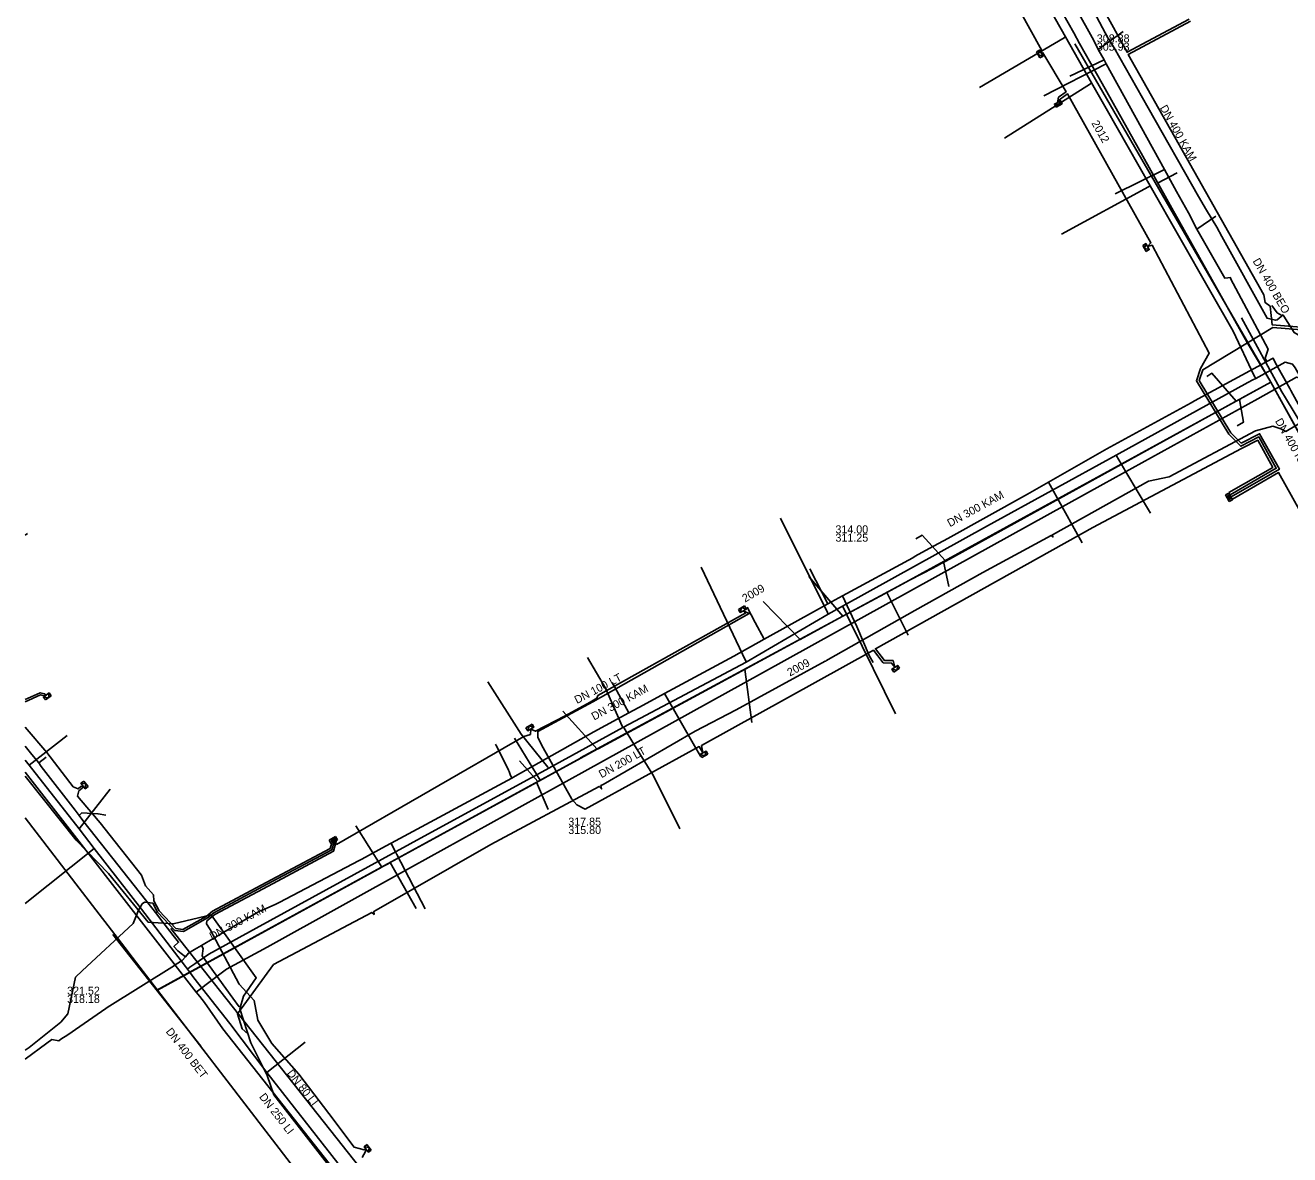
# Model space of a CAD drawing. Extents: x -600391 to -599491, y -1160176 to -1159402.
# Drawn here: x -600391 to -600264.6, y -1159907.9 to -1159795.1 of the extents above; entities that cross this region are included whole.
import ezdxf

# ---------------------------------------------------------------- set-up
doc = ezdxf.new("R2010")
doc.units = 0
for name, color, linetype in [('28', 7, 'Continuous'), ('31', 7, 'Continuous'), ('Vrstva 1', 7, 'Continuous'), ('Vrstva 12', 7, 'Continuous'), ('Vrstva 13', 7, 'Continuous'), ('Vrstva 15', 7, 'Continuous'), ('Vrstva 16', 7, 'Continuous'), ('Vrstva 19', 7, 'Continuous'), ('Vrstva 42', 7, 'Continuous'), ('Vrstva 43', 7, 'Continuous'), ('Vrstva 55', 7, 'Continuous'), ('Vrstva 9', 7, 'Continuous')]:
    doc.layers.add(name, color=color, linetype=linetype)

# ---------------------------------------------------------------- blocks, each defined once
blk = doc.blocks.new('NN630')
at = {"layer": '31'}
for points in [[(0, -0.7), (-0.7, 0)], [(-0.7, -0.7), (-0.7, 0), (0.7, 0), (0.7, -0.7)], [(-0.7, -0.7), (0.7, -0.7)], [(0, -0.7), (0.7, 0)]]:
    blk.add_lwpolyline(points, dxfattribs=at)
blk = doc.blocks.new('NN620')
at = {"layer": '28'}
for points in [[(0.75, 0), (-0.75, 0)], [(-0.75, 0), (-0.75, -0.75)], [(0.75, -0.75), (0.75, 0)], [(-0.75, -0.75), (0.75, -0.75)], [(0.37, -0.18), (-0.38, -0.18)], [(-0.38, -0.18), (-0.38, -0.56)], [(-0.38, -0.56), (0.37, -0.56)], [(0.32, -0.23), (-0.33, -0.23)], [(-0.33, -0.23), (-0.33, -0.51)], [(-0.33, -0.51), (0.32, -0.51)], [(0.27, -0.27), (-0.28, -0.27)], [(-0.28, -0.27), (-0.28, -0.46)], [(-0.28, -0.46), (0.27, -0.46)], [(0.23, -0.32), (-0.23, -0.32)], [(-0.23, -0.32), (-0.23, -0.42)], [(-0.23, -0.42), (0.23, -0.42)], [(-0.19, -0.37), (0.19, -0.37)], [(0.23, -0.42), (0.23, -0.32)], [(0.27, -0.46), (0.27, -0.27)], [(0.32, -0.51), (0.32, -0.23)], [(0.37, -0.56), (0.37, -0.18)]]:
    blk.add_lwpolyline(points, dxfattribs=at)

msp = doc.modelspace()

# ---------------------------------------------------------------- linework, layer by layer
at = {"layer": 'Vrstva 1'}
for points in [[(-600266.53, -1159830.73), (-600286.12, -1159796.92)], [(-600275.88, -1159809.81), (-600277.84, -1159810.83)], [(-600272.94, -1159830.17), (-600272.41, -1159829.84), (-600269.98, -1159832.62)], [(-600266.53, -1159830.73), (-600302.63, -1159850.52)], [(-600254.35, -1159852.71), (-600266.53, -1159830.73)], [(-600269.9, -1159835.08), (-600269.27, -1159834.73), (-600269.67, -1159832.45)], [(-600299.06, -1159848.55), (-600301.38, -1159846.02), (-600302.01, -1159846.37)], [(-600299.24, -1159848.65), (-600298.7, -1159851.13)], [(-600302.63, -1159850.52), (-600335.52, -1159868.27)], [(-600309.3, -1159854.11), (-600312.71, -1159850.14)], [(-600304.91, -1159851.74), (-600302.76, -1159856.02)], [(-600313.58, -1159856.42), (-600317.27, -1159852.64)], [(-600318.41, -1159864.72), (-600319.08, -1159859.39)], [(-600333.86, -1159867.38), (-600337.27, -1159863.61)], [(-600339.56, -1159870.49), (-600342.12, -1159866.31)], [(-600335.52, -1159868.28), (-600377.87, -1159891.49)], [(-600339.77, -1159870.61), (-600341.61, -1159868.57)], [(-600339.93, -1159870.7), (-600338.76, -1159873.42)], [(-600357.98, -1159875.06), (-600355.38, -1159879.17)], [(-600354.54, -1159878.71), (-600351.94, -1159883.33)], [(-600382.26, -1159885.91), (-600373.48, -1159897.07)]]:
    msp.add_lwpolyline(points, dxfattribs=at)
at = {"layer": 'Vrstva 13'}
for p, q in [((-600270.29, -1159825.64), (-600268.19, -1159830.08)), ((-600268.32, -1159830.5), (-600268.04, -1159830.35)), ((-600268.19, -1159830.08), (-600268.04, -1159830.35)), ((-600391.01, -1159846.01), (-600390.8, -1159845.85)), ((-600390.63, -1159868.99), (-600386.81, -1159866.03)), ((-600385.63, -1159875.35), (-600382.53, -1159871.38)), ((-600384.14, -1159877.32), (-600391.01, -1159882.83)), ((-600379.39, -1159883.39), (-600375.01, -1159889.1)), ((-600378.45, -1159885.84), (-600373.92, -1159891.66)), ((-600375.01, -1159889.1), (-600374.8, -1159889.38)), ((-600374.8, -1159889.38), (-600374.55, -1159889.19)), ((-600374.8, -1159889.38), (-600374.6, -1159889.65)), ((-600374.6, -1159889.65), (-600374.51, -1159889.78)), ((-600373.92, -1159891.66), (-600373.54, -1159891.36)), ((-600373.92, -1159891.66), (-600373.56, -1159892.11)), ((-600366.86, -1159899.69), (-600363.05, -1159896.67))]:
    msp.add_line(p, q, dxfattribs=at)
for points in [[(-600318.46, -1159740.43), (-600311.31, -1159753.11), (-600311.18, -1159753.34), (-600308.82, -1159757.52), (-600308.39, -1159758.3), (-600301.63, -1159770.35), (-600298.43, -1159776.06), (-600297.79, -1159777.2), (-600296.56, -1159779.37), (-600292.54, -1159786.5), (-600291.67, -1159788.04), (-600288.04, -1159794.45), (-600287.04, -1159796.22), (-600284.44, -1159800.82), (-600282.98, -1159803.38), (-600278.58, -1159811.11), (-600272.65, -1159821.5), (-600270.29, -1159825.64)], [(-600287.04, -1159796.22), (-600287.19, -1159796.31), (-600295.64, -1159801.28)], [(-600284.44, -1159800.82), (-600284.56, -1159800.9), (-600293.16, -1159806.35)], [(-600278.58, -1159811.11), (-600278.75, -1159811.21), (-600287.46, -1159815.94)], [(-600268.04, -1159830.35), (-600265.11, -1159828.73), (-600264.36, -1159828.93), (-600264.11, -1159829.29), (-600263.68, -1159829.99), (-600263.48, -1159830.35), (-600250.95, -1159852.35), (-600246.5, -1159860.12), (-600238.23, -1159874.5), (-600236.83, -1159876.89), (-600236.21, -1159877.98)], [(-600374.55, -1159889.19), (-600374.05, -1159888.85), (-600372.67, -1159887.87), (-600367.94, -1159885.27), (-600352.53, -1159876.85), (-600338.69, -1159869.28), (-600331.3, -1159865.24), (-600331.21, -1159865.2), (-600318.95, -1159858.71), (-600310.78, -1159853.89), (-600309.34, -1159853.1), (-600294.83, -1159845.09), (-600281.99, -1159838.01), (-600268.81, -1159830.77), (-600268.32, -1159830.5)], [(-600373.54, -1159891.36), (-600372.93, -1159890.91), (-600370.89, -1159889.39), (-600366.85, -1159887.18), (-600352.31, -1159879.13), (-600335.08, -1159869.59), (-600317.34, -1159859.78), (-600300.08, -1159850.22), (-600283.27, -1159840.92), (-600267.84, -1159832.38), (-600263.95, -1159830.23), (-600262.43, -1159830.62), (-600255.08, -1159843.6), (-600247.73, -1159856.58), (-600236, -1159876.75), (-600235.14, -1159876.86), (-600231.99, -1159875.01), (-600217.64, -1159866.82), (-600199.23, -1159856.44), (-600175.64, -1159843.1), (-600159.56, -1159834.39), (-600159.03, -1159834.09)], [(-600281.99, -1159838.01), (-600281.94, -1159838.1), (-600281.01, -1159839.67), (-600278.54, -1159843.82)], [(-600310.78, -1159853.89), (-600310.85, -1159853.75), (-600315.54, -1159844.31)], [(-600318.95, -1159858.71), (-600319, -1159858.61), (-600323.47, -1159849.2)], [(-600309.34, -1159853.1), (-600309.28, -1159853.22), (-600308.47, -1159854.87), (-600304.04, -1159863.86)], [(-600331.3, -1159865.24), (-600331.36, -1159865.1), (-600333.02, -1159861.3), (-600334.83, -1159858.24)], [(-600338.69, -1159869.28), (-600338.77, -1159869.18), (-600341.44, -1159865.88), (-600344.79, -1159860.67)], [(-600331.21, -1159865.2), (-600331.17, -1159865.28), (-600330.18, -1159866.89), (-600328.24, -1159870.07), (-600325.59, -1159875.36)], [(-600391.01, -1159868.51), (-600390.63, -1159868.99), (-600385.63, -1159875.35), (-600384.14, -1159877.32), (-600379.39, -1159883.39)], [(-600391.01, -1159869.68), (-600384.73, -1159877.8), (-600378.45, -1159885.84)], [(-600374.51, -1159889.78), (-600374.17, -1159890.23), (-600370.56, -1159894.82)], [(-600373.56, -1159892.11), (-600373.11, -1159892.72), (-600371.27, -1159895.33)], [(-600370.56, -1159894.82), (-600366.86, -1159899.69), (-600357.62, -1159911.54), (-600356.84, -1159912.52), (-600341.12, -1159932.99), (-600339.37, -1159935.25), (-600334.21, -1159941.97), (-600326.67, -1159951.39), (-600325.09, -1159953.46), (-600321.88, -1159957.77), (-600316.54, -1159964.25), (-600309.48, -1159972.8)], [(-600371.27, -1159895.33), (-600358.15, -1159911.95), (-600339.79, -1159935.58), (-600327.19, -1159951.77), (-600317.13, -1159964.71), (-600308.66, -1159975.6)]]:
    msp.add_lwpolyline(points, dxfattribs=at)
at = {"layer": 'Vrstva 16'}
msp.add_lwpolyline([(-600149.13, -1160176.08), (-600149.77, -1160175.26), (-600153.28, -1160170.92), (-600160.82, -1160161.59), (-600162.37, -1160159.57), (-600191.81, -1160121.42), (-600215.03, -1160091.66), (-600218.37, -1160087.39), (-600241.27, -1160058.04), (-600268.45, -1160023.15), (-600268.66, -1160022.86), (-600279.96, -1160008.45), (-600285.15, -1160001.76), (-600292.76, -1159991.95), (-600306.26, -1159974.55), (-600310.89, -1159968.58), (-600323.17, -1159952.95), (-600331.19, -1159942.75), (-600331.3, -1159942.61), (-600336.91, -1159935.47), (-600352.95, -1159915.04), (-600356.32, -1159910.78), (-600372.09, -1159890.83), (-600376.45, -1159885.3)], dxfattribs=at)
at = {"layer": 'Vrstva 19'}
for points in [[(-600287.66, -1159790.4), (-600284.23, -1159796.59), (-600283.8, -1159797.49), (-600283.17, -1159798.5), (-600283, -1159798.92), (-600277.16, -1159809.47), (-600275.95, -1159811.66), (-600274.75, -1159813.8), (-600273.93, -1159815.43), (-600271.13, -1159820.33), (-600270.53, -1159820.26)], [(-600283.8, -1159797.49), (-600281.29, -1159795.68)], [(-600283, -1159798.92), (-600289.2, -1159802.12)], [(-600283.17, -1159798.5), (-600286.61, -1159800.15)], [(-600277.16, -1159809.47), (-600282.08, -1159811.91)], [(-600273.93, -1159815.43), (-600272.01, -1159814.14)], [(-600266.92, -1159828.65), (-600267.09, -1159828.33), (-600266.8, -1159827.42), (-600270.55, -1159820.36), (-600270.53, -1159820.26)], [(-600261.41, -1159838.35), (-600265.07, -1159832.29), (-600265.42, -1159831.69), (-600269.46, -1159824.28)], [(-600266.92, -1159828.65), (-600267.46, -1159828.95), (-600274.14, -1159832.6), (-600274.49, -1159832.78), (-600282.92, -1159837.39), (-600288.74, -1159840.73), (-600290.83, -1159841.93), (-600298.81, -1159846.33), (-600300.68, -1159847.36), (-600302.06, -1159848.12), (-600302.31, -1159848.26), (-600309.33, -1159852.07), (-600310.8, -1159852.87), (-600311.95, -1159853.5), (-600317.17, -1159856.4), (-600320.2, -1159858.09), (-600327.11, -1159861.82), (-600329.27, -1159862.99), (-600330.7, -1159863.77), (-600334.2, -1159865.67), (-600342.04, -1159870.09), (-600342.37, -1159870.28), (-600354.44, -1159876.78), (-600355.01, -1159877.09), (-600357.38, -1159878.39), (-600357.64, -1159878.53), (-600365.63, -1159882.7)], [(-600235.81, -1159871.96), (-600240.31, -1159874.37), (-600240.85, -1159873.47), (-600242.66, -1159870.41), (-600247.12, -1159862.9), (-600248.85, -1159859.8), (-600250.34, -1159857.14), (-600257.66, -1159844.02), (-600258.74, -1159842.09), (-600261.4, -1159837.25), (-600264.53, -1159831.56), (-600264.64, -1159831.36), (-600266.08, -1159828.75), (-600266.31, -1159828.32), (-600266.92, -1159828.65)], [(-600288.74, -1159840.73), (-600286.01, -1159845.66), (-600285.39, -1159846.78)], [(-600310.8, -1159852.87), (-600312.61, -1159849.38)], [(-600309.33, -1159852.07), (-600307.9, -1159855.13), (-600306.66, -1159858.05), (-600306.26, -1159858.72)], [(-600317.17, -1159856.4), (-600318.06, -1159854.75), (-600318.86, -1159853.19)], [(-600330.7, -1159863.77), (-600332.1, -1159861.2), (-600332.35, -1159860.74)], [(-600327.11, -1159861.82), (-600323.99, -1159867.3), (-600323.53, -1159868.11)], [(-600391.01, -1159867.1), (-600390.36, -1159867.94), (-600389.67, -1159868.77), (-600389.43, -1159869.12), (-600386.03, -1159873.48), (-600385.62, -1159874.01), (-600385.17, -1159874.66), (-600377.87, -1159883.89), (-600377.29, -1159884.64), (-600377.14, -1159884.84)], [(-600344, -1159866.91), (-600343.95, -1159867.02), (-600343.19, -1159868.54), (-600342.72, -1159869.48)], [(-600389.67, -1159868.77), (-600388.92, -1159868.2)], [(-600342.72, -1159869.48), (-600342.64, -1159869.64), (-600342.56, -1159869.92), (-600342.37, -1159870.28)], [(-600385.62, -1159874.01), (-600385.37, -1159873.76), (-600383.77, -1159873.87), (-600383.71, -1159873.84)], [(-600383.71, -1159873.84), (-600382.95, -1159873.99)], [(-600354.44, -1159876.78), (-600354.26, -1159877.14), (-600354, -1159877.65), (-600353.87, -1159877.91)], [(-600353.87, -1159877.91), (-600351.06, -1159883.36)], [(-600365.63, -1159882.7), (-600366.04, -1159882.9), (-600367.16, -1159883.43), (-600367.53, -1159883.54), (-600371.16, -1159885.68), (-600372.18, -1159886.28), (-600373.4, -1159887)], [(-600375.44, -1159887.8), (-600375.76, -1159887.54), (-600376.15, -1159887.12), (-600375.68, -1159886.69), (-600376.24, -1159886.02), (-600377.14, -1159884.84)], [(-600373.4, -1159887), (-600374.09, -1159887.42), (-600374.7, -1159887.79), (-600375, -1159888.14), (-600375.32, -1159888.51), (-600375.93, -1159888.89), (-600376.11, -1159889), (-600382.81, -1159893.22), (-600382.96, -1159893.32), (-600385.56, -1159895.1), (-600386.77, -1159895.94), (-600387.45, -1159896.37)], [(-600373.4, -1159887), (-600373.22, -1159887.31), (-600373.34, -1159888.03), (-600370.28, -1159892.26), (-600369.64, -1159893.15)], [(-600375, -1159888.14), (-600375.44, -1159887.8)], [(-600391.01, -1159898.38), (-600388.84, -1159896.76), (-600388.36, -1159896.41), (-600387.64, -1159896.53), (-600387.45, -1159896.37)]]:
    msp.add_lwpolyline(points, dxfattribs=at)
at = {"layer": 'Vrstva 42'}
for points in [[(-600294.74, -1159787.93), (-600289.43, -1159797.58), (-600289.47, -1159797.84), (-600289.31, -1159797.8), (-600286.99, -1159801.7), (-600287.76, -1159802.26), (-600287.84, -1159802.77), (-600287.57, -1159802.43), (-600286.86, -1159801.91), (-600278.52, -1159816.81), (-600278.85, -1159817.18), (-600278.4, -1159817.03), (-600272.68, -1159827.82), (-600273.54, -1159829.37), (-600273.96, -1159830.59), (-600270.71, -1159835.93), (-600269.53, -1159837.12), (-600267.74, -1159836.19), (-600265.99, -1159839.33), (-600270.6, -1159841.98)], [(-600274.69, -1159794.44), (-600280.89, -1159797.76), (-600283.41, -1159793.2)], [(-600259.4, -1159825.56), (-600266.4, -1159824.99), (-600266.61, -1159823.13), (-600267.1, -1159822.77), (-600267.22, -1159821.98), (-600280.77, -1159797.98), (-600274.56, -1159794.65)], [(-600248.79, -1159820.17), (-600250.58, -1159821.13), (-600259.35, -1159825.82), (-600266.34, -1159825.25), (-600273.31, -1159829.48), (-600273.68, -1159830.56), (-600270.51, -1159835.78), (-600269.48, -1159836.81), (-600267.65, -1159835.87), (-600265.67, -1159839.42), (-600270.48, -1159842.19)], [(-600270.72, -1159841.76), (-600266.33, -1159839.24), (-600267.84, -1159836.52), (-600269.46, -1159837.36), (-600284.32, -1159845.24), (-600306.04, -1159857.36), (-600305.14, -1159858.52), (-600304.28, -1159858.55), (-600304.11, -1159859.21), (-600304.43, -1159858.8), (-600305.27, -1159858.77), (-600306.25, -1159857.51), (-600323.42, -1159867.03), (-600323.28, -1159867.76), (-600323.65, -1159867.14), (-600335.04, -1159873.39), (-600335.9, -1159872.95), (-600336.4, -1159872.39), (-600339.41, -1159866.96), (-600339.79, -1159866.21), (-600339.77, -1159865.62), (-600334.3, -1159862.66), (-600318.65, -1159853.85), (-600319.25, -1159853.56), (-600319, -1159853.76), (-600333.8, -1159862.04), (-600333.9, -1159862.3), (-600334.57, -1159862.7)], [(-600257.34, -1159854.85), (-600265.75, -1159839.76), (-600270.36, -1159842.41)], [(-600391.01, -1159862.66), (-600389.5, -1159861.96), (-600389.13, -1159862.05), (-600388.91, -1159861.99), (-600389.08, -1159861.85), (-600389.52, -1159861.76), (-600391.01, -1159862.44)], [(-600334.57, -1159862.7), (-600337.06, -1159864.05), (-600340.03, -1159865.61), (-600340.49, -1159865.38)], [(-600384.87, -1159873.18), (-600385.79, -1159872.1), (-600385.65, -1159871.57), (-600385.32, -1159871.29), (-600385.23, -1159871.08), (-600385.45, -1159871.14), (-600385.71, -1159871.36), (-600386.22, -1159871.16), (-600388.86, -1159867.74), (-600391.01, -1159865.18)], [(-600340.49, -1159865.38), (-600340.53, -1159865.92), (-600341.17, -1159866.14), (-600359.89, -1159876.91), (-600360.07, -1159876.58)], [(-600360.37, -1159876.74), (-600360.53, -1159877.32), (-600366.92, -1159880.72), (-600372.29, -1159883.57), (-600372.93, -1159884.1), (-600375.25, -1159885.43), (-600375.97, -1159885.33), (-600377.64, -1159883.55), (-600378.15, -1159882.55), (-600378.2, -1159881.94), (-600379, -1159881.04), (-600379.38, -1159879.97), (-600383.53, -1159874.75), (-600384.87, -1159873.18)], [(-600391.01, -1159897.47), (-600390.61, -1159897.2), (-600387.46, -1159894.66), (-600386.75, -1159893.85), (-600385.98, -1159890.18), (-600385.33, -1159889.53), (-600380.24, -1159884.8), (-600379.7, -1159883.47), (-600379.33, -1159882.85), (-600379.08, -1159882.68), (-600378.25, -1159882.79), (-600377.8, -1159883.67), (-600376.07, -1159885.51), (-600375.21, -1159885.63), (-600372.8, -1159884.25), (-600372.18, -1159883.74), (-600366.83, -1159880.9), (-600360.36, -1159877.46), (-600360.14, -1159876.64)], [(-600357.33, -1159908.2), (-600357.02, -1159907.6), (-600356.92, -1159907.4), (-600357.14, -1159907.44), (-600358.14, -1159907.17), (-600360.67, -1159903.79), (-600363.68, -1159899.86), (-600366.37, -1159896.82), (-600367.77, -1159894.49), (-600368.15, -1159892.52), (-600369.63, -1159890.89), (-600372.54, -1159885.4), (-600372.89, -1159884.84), (-600372.85, -1159884.55), (-600372.07, -1159883.91), (-600366.74, -1159881.08), (-600360.19, -1159877.6), (-600359.9, -1159876.5)]]:
    msp.add_lwpolyline(points, dxfattribs=at)
at = {"layer": 'Vrstva 55'}
for points in [[(-600265.28, -1159823.98), (-600265.89, -1159824.48), (-600266.05, -1159824.53), (-600266.9, -1159824.34), (-600271.42, -1159816.18), (-600271.94, -1159815.25), (-600272.96, -1159813.53), (-600273.74, -1159812.17), (-600278.8, -1159803.3), (-600282.17, -1159797.33), (-600282.81, -1159796.3), (-600284.17, -1159793.74)], [(-600265.28, -1159823.98), (-600265.42, -1159824.05), (-600265.89, -1159823.8), (-600266.43, -1159823.05)], [(-600256.57, -1159830.38), (-600257.98, -1159831.14), (-600259.24, -1159828.63), (-600264.18, -1159825.77), (-600265.22, -1159824.13), (-600265.28, -1159823.98)], [(-600258.8, -1159831.94), (-600265.03, -1159835.65), (-600265.52, -1159835.4), (-600266.32, -1159835.12), (-600268.06, -1159835.58), (-600276.69, -1159840.17), (-600278.74, -1159840.6), (-600288.36, -1159845.97), (-600288.31, -1159846.18), (-600288.48, -1159846.04), (-600295.31, -1159849.74), (-600302.11, -1159853.54), (-600310.77, -1159858.45), (-600310.95, -1159858.55), (-600311, -1159858.6), (-600311.06, -1159858.6), (-600319.96, -1159863.45), (-600324.06, -1159865.58), (-600333.27, -1159870.91), (-600333.48, -1159871.03), (-600333.41, -1159871.37), (-600333.65, -1159871.12), (-600344.48, -1159876.93), (-600355.93, -1159883.48), (-600356.17, -1159883.61), (-600356.15, -1159883.91), (-600356.36, -1159883.71), (-600366.2, -1159888.91), (-600369.8, -1159893.83), (-600369.33, -1159895.33), (-600368.76, -1159895.84)], [(-600349.16, -1159923.81), (-600366.16, -1159901.93), (-600366.85, -1159899.99), (-600368.47, -1159896.75), (-600369.55, -1159893.33), (-600369.19, -1159892.06), (-600367.93, -1159890.26), (-600372.44, -1159883.96), (-600376.22, -1159884.86), (-600378.74, -1159884.68), (-600382.7, -1159879.82), (-600385.93, -1159876.49), (-600391.01, -1159870.08)]]:
    msp.add_lwpolyline(points, dxfattribs=at)
at = {"layer": 'Vrstva 9'}
msp.add_line((-600266.53, -1159830.73), (-600268.89, -1159826.76), dxfattribs=at)
for points in [[(-600286.22, -1159795.83), (-600287.92, -1159792.81), (-600289.01, -1159790.9), (-600294.13, -1159781.81), (-600294.58, -1159781.01), (-600300, -1159771.38), (-600300.37, -1159770.73), (-600302.46, -1159767.03)], [(-600268.89, -1159826.76), (-600276.42, -1159813.32), (-600278.23, -1159810.1), (-600283.39, -1159800.89), (-600285.64, -1159796.88), (-600286.22, -1159795.83)], [(-600302.58, -1159850.48), (-600300.32, -1159849.32), (-600299.63, -1159848.94), (-600299.23, -1159848.71), (-600299.2, -1159848.7), (-600299.02, -1159848.6), (-600270.11, -1159832.69), (-600269.98, -1159832.62), (-600269.67, -1159832.45), (-600269.39, -1159832.29), (-600266.53, -1159830.73)], [(-600254.33, -1159852.65), (-600259.54, -1159843.35), (-600259.58, -1159843.27), (-600261, -1159840.7), (-600261.02, -1159840.68), (-600266.53, -1159830.73)], [(-600335.49, -1159868.28), (-600333.84, -1159867.4), (-600333.76, -1159867.35), (-600319.07, -1159859.4), (-600319.06, -1159859.39), (-600313.68, -1159856.48), (-600313.57, -1159856.43), (-600310.47, -1159854.75), (-600309.29, -1159854.11), (-600305.13, -1159851.86), (-600304.91, -1159851.74), (-600302.58, -1159850.48)], [(-600377.81, -1159891.47), (-600355.37, -1159879.18), (-600355.29, -1159879.13), (-600354.81, -1159878.87), (-600354.54, -1159878.72), (-600339.93, -1159870.71), (-600339.76, -1159870.62), (-600339.55, -1159870.51), (-600339.33, -1159870.38), (-600338.8, -1159870.09), (-600338.36, -1159869.85), (-600335.49, -1159868.28)], [(-600391.01, -1159874.25), (-600385.62, -1159881.28), (-600380.74, -1159887.64), (-600380.67, -1159887.74), (-600377.81, -1159891.47)], [(-600377.81, -1159891.47), (-600355.47, -1159920.53), (-600347.2, -1159931.29), (-600347.12, -1159931.4), (-600346.8, -1159931.81)]]:
    msp.add_lwpolyline(points, dxfattribs=at)

# ---------------------------------------------------------------- block references
at = {"layer": 'Vrstva 43'}
for name, p, xscale, yscale, rotation in [('NN630', (-600289.47, -1159797.84), 0.5, 0.5, -59.99999999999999), ('NN630', (-600287.84, -1159802.77), 0.5000000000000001, 0.4999999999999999, 28), ('NN630', (-600278.85, -1159817.18), 0.5, 0.5, -59.99999999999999), ('NN620', (-600270.54, -1159842.14), 0.5, 0.5, -61.000000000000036), ('NN630', (-600319.25, -1159853.56), 0.5000000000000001, 0.4999999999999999, -151), ('NN630', (-600304.11, -1159859.21), 0.5000000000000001, 0.5, 32.99999999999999), ('NN630', (-600388.91, -1159861.99), 0.5, 0.5, 37), ('NN630', (-600340.49, -1159865.38), 0.5, 0.5, -150.00000000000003), ('NN630', (-600323.28, -1159867.76), 0.5, 0.5, 29.999999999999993), ('NN630', (-600385.23, -1159871.08), 0.5, 0.5, 128), ('NN620', (-600360.14, -1159876.64), 0.5, 0.5, -150.00000000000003), ('NN630', (-600356.92, -1159907.4), 0.5, 0.5, 128)]:
    msp.add_blockref(name, p, dxfattribs=dict(at, xscale=xscale, yscale=yscale, rotation=rotation))

# ---------------------------------------------------------------- texts
at = {"layer": 'Vrstva 12'}
for s, p in [('308.88', (-600283.92, -1159796.77)), ('305.93', (-600283.92, -1159797.6)), ('314.00', (-600310.04, -1159845.83)), ('311.25', (-600310.04, -1159846.66)), ('317.85', (-600336.74, -1159875.04)), ('315.80', (-600336.74, -1159875.87)), ('321.52', (-600386.83, -1159891.93)), ('318.18', (-600386.83, -1159892.76))]:
    msp.add_text(s, height=0.8, dxfattribs=at).set_placement(p)
for s, rotation, p in [('DN 400 KAM', 299.2767, (-600277.64, -1159803.3)), ('DN 400 BEO', 300.1153, (-600268.37, -1159818.62)), ('DN 400 KAM', 299.2559, (-600266.13, -1159834.6)), ('DN 300 KAM', 28.5906, (-600298.6, -1159845.22)), ('DN 300 KAM', 28.2468, (-600334.16, -1159864.54)), ('DN 300 KAM', 28.1895, (-600372.34, -1159886.51)), ('DN 400 BET', 307.5637, (-600377.01, -1159895.62))]:
    msp.add_text(s, height=0.8, rotation=rotation, dxfattribs=at).set_placement(p)
at = {"layer": 'Vrstva 15'}
for s, rotation, p in [('2012', 299.5094, (-600284.48, -1159804.84)), ('2009', 30.5387, (-600319.07, -1159852.75)), ('2009', 28.9917, (-600314.59, -1159860.15)), ('DN 100 LT', 27.8457, (-600335.87, -1159862.89)), ('DN 200 LT', 28.9344, (-600333.42, -1159870.31)), ('DN 80 LI', 307.9648, (-600364.91, -1159899.79)), ('DN 250 LI', 307.8502, (-600367.68, -1159902.15))]:
    msp.add_text(s, height=0.8, rotation=rotation, dxfattribs=at).set_placement(p)

doc.saveas('drawing.dxf')
